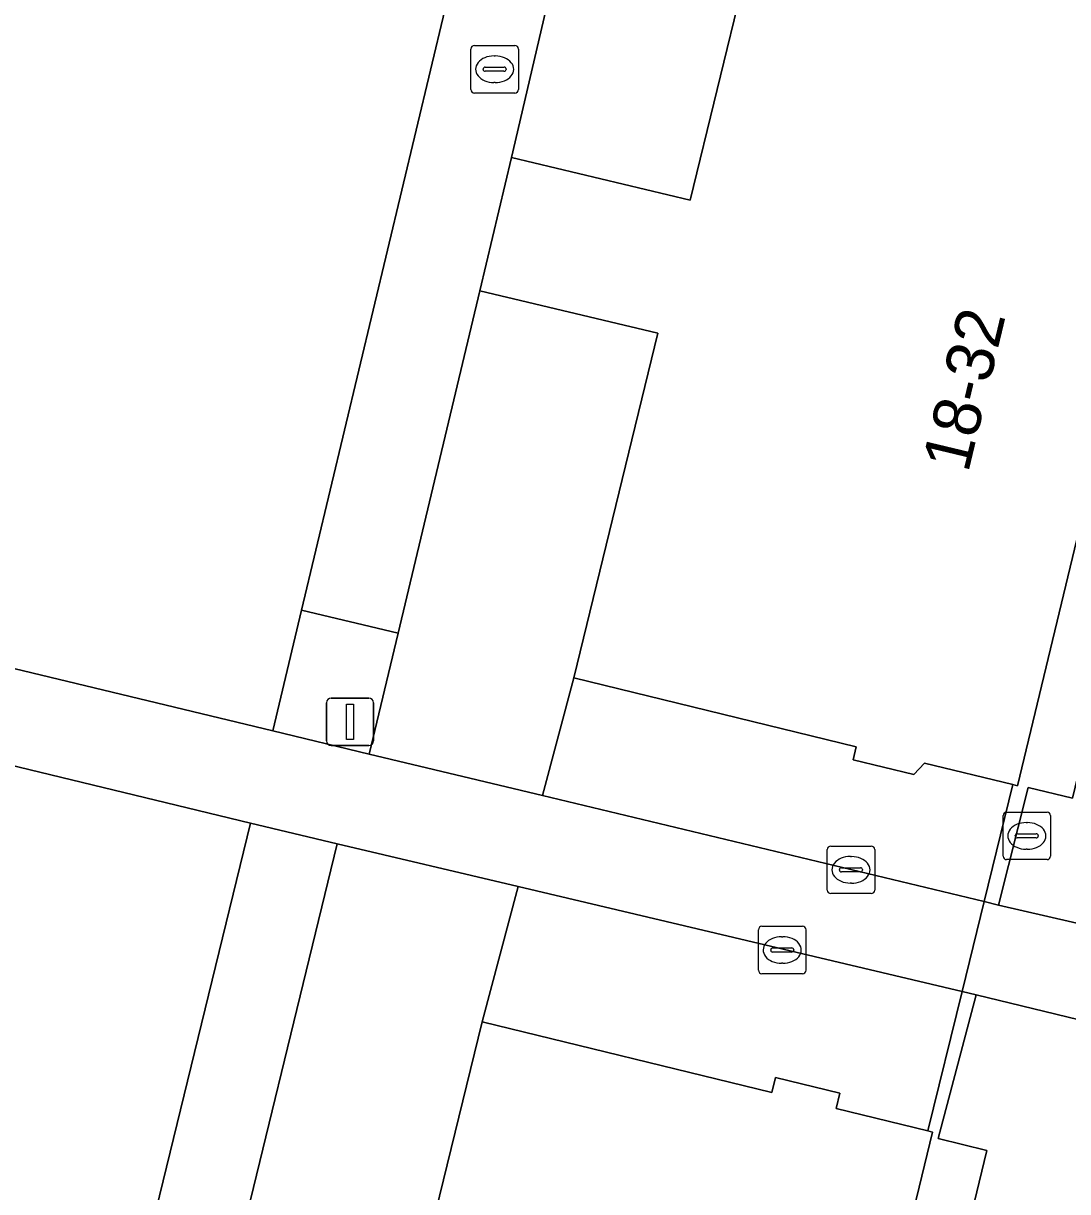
# Model space of a CAD drawing. Extents: x 162803 to 163818, y 381639 to 382475.
# Drawn here: x 163067.19 to 163089.17, y 382297.45 to 382322.05 of the extents above; entities that cross this region are included whole.
import ezdxf

# ---------------------------------------------------------------- set-up
doc = ezdxf.new("R2010")
doc.units = 0
for name, color, linetype in [('IMGEO_Erf', 7, 'Continuous'), ('IMGEO_Hek', 7, 'Continuous'), ('IMGEO_Kolk', 7, 'Continuous'), ('IMGEO_Lichtmast', 7, 'Continuous'), ('IMGEO_Pand', 7, 'Continuous'), ('IMGEO_Pand_nummerreeks', 7, 'Continuous'), ('IMGEO_Rijbaan_lokaal_open', 7, 'Continuous'), ('IMGEO_Rioolput', 7, 'Continuous'), ('IMGEO_Voetpad_open', 7, 'Continuous')]:
    doc.layers.add(name, color=color, linetype=linetype)

msp = doc.modelspace()

# ---------------------------------------------------------------- linework, layer by layer
at = {"layer": 'IMGEO_Erf'}
for points in [[(163047.148, 382313.237), (163050.064, 382312.535), (163072.437, 382307.153), (163073.044, 382309.695), (163078.774, 382333.702), (163080.732, 382333.247), (163081.463, 382336.312), (163085.348, 382335.385), (163086.911, 382341.81), (163082.923, 382342.771), (163082.98, 382343.013), (163078.703, 382344.022), (163078.603, 382343.596), (163074.714, 382344.513)], [(163048.239, 382218.67), (163052.52, 382217.651), (163052.587, 382217.933), (163056.662, 382216.932), (163057.383, 382219.931), (163058.384, 382224.091), (163054.451, 382225.06), (163052.509, 382225.538), (163058.483, 382250), (163071.966, 382305.208), (163049.551, 382310.636), (163046.613, 382311.37)]]:
    msp.add_lwpolyline(points, dxfattribs=at)
for points in [[(163084.627, 382332.317), (163080.732, 382333.247), (163077.463, 382319.223), (163081.222, 382318.327), (163082.925, 382325.322)], [(163080.542, 382315.527), (163076.795, 382316.421), (163075.074, 382309.213), (163074.466, 382306.666), (163078.114, 382305.79), (163078.775, 382308.268)], [(163086.158, 382306.473), (163085.931, 382306.236), (163084.652, 382306.547), (163084.719, 382306.821), (163078.775, 382308.268), (163078.114, 382305.79), (163087.41, 382303.559), (163088.014, 382306.022)], [(163076.842, 382301.026), (163077.602, 382303.874), (163073.795, 382304.774), (163071.315, 382294.597), (163075.048, 382293.685)], [(163086.946, 382301.665), (163077.602, 382303.874), (163076.842, 382301.026), (163082.941, 382299.537), (163083.02, 382299.859), (163084.377, 382299.528), (163084.297, 382299.201), (163086.227, 382298.73)]]:
    msp.add_lwpolyline(points, close=True, dxfattribs=at)
at = {"layer": 'IMGEO_Hek'}
for points in [[(163088.014, 382306.022), (163087.41, 382303.559)], [(163087.41, 382303.559), (163086.946, 382301.665)], [(163086.946, 382301.665), (163086.227, 382298.73)]]:
    msp.add_lwpolyline(points, dxfattribs=at)
at = {"layer": 'IMGEO_Kolk'}
for p, q in [((163084.182, 382304.728), (163085.034, 382304.728)), ((163084.107, 382303.802), (163084.107, 382304.654)), ((163084.595, 382304.508), (163084.62, 382304.508)), ((163085.108, 382304.654), (163085.108, 382303.802)), ((163084.366, 382304.222), (163084.366, 382304.234)), ((163084.409, 382304.271), (163084.807, 382304.271)), ((163084.85, 382304.234), (163084.85, 382304.222)), ((163084.804, 382304.185), (163084.406, 382304.185)), ((163085.034, 382303.728), (163084.182, 382303.728)), ((163084.618, 382303.948), (163084.593, 382303.948)), ((163082.735, 382303.04), (163083.587, 382303.04)), ((163082.66, 382302.114), (163082.66, 382302.966)), ((163083.148, 382302.82), (163083.173, 382302.82)), ((163083.661, 382302.966), (163083.661, 382302.114)), ((163082.919, 382302.534), (163082.919, 382302.546)), ((163083.357, 382302.497), (163082.959, 382302.497)), ((163082.962, 382302.583), (163083.36, 382302.583)), ((163083.403, 382302.546), (163083.403, 382302.534)), ((163083.171, 382302.26), (163083.146, 382302.26)), ((163083.587, 382302.04), (163082.735, 382302.04))]:
    msp.add_line(p, q, dxfattribs=at)
for points in [[(163084.182, 382304.728), (163085.034, 382304.728)], [(163084.107, 382303.802), (163084.107, 382304.654)], [(163085.108, 382304.654), (163085.108, 382303.802)], [(163085.034, 382303.728), (163084.182, 382303.728)], [(163082.735, 382303.04), (163083.587, 382303.04)], [(163082.66, 382302.114), (163082.66, 382302.966)], [(163083.661, 382302.966), (163083.661, 382302.114)], [(163083.587, 382302.04), (163082.735, 382302.04)]]:
    msp.add_lwpolyline(points, dxfattribs=at)
for centre, radius, start, end in [((163084.184, 382304.652), 0.0765, 91.552, 178.448), ((163084.184, 382304.652), 0.0765, 91.552, 178.448), ((163085.032, 382304.652), 0.0765, 1.552, 88.448), ((163085.032, 382304.652), 0.0765, 1.552, 88.448), ((163084.406, 382304.231), 0.0403, 85.8775, 175.7526), ((163084.403, 382304.221), 0.0366, 178.938, 274.7102), ((163084.807, 382304.228), 0.043, 264.8664, 352.4533), ((163084.811, 382304.233), 0.0386, 1.7309, 96.639), ((163084.184, 382303.804), 0.0765, 181.552, 268.448), ((163084.184, 382303.804), 0.0765, 181.552, 268.448), ((163085.032, 382303.804), 0.0765, 271.552, 358.448), ((163085.032, 382303.804), 0.0765, 271.552, 358.448), ((163082.737, 382302.964), 0.0765, 91.552, 178.448), ((163082.737, 382302.964), 0.0765, 91.552, 178.448), ((163083.585, 382302.964), 0.0765, 1.552, 88.448), ((163083.585, 382302.964), 0.0765, 1.552, 88.448), ((163082.959, 382302.543), 0.0403, 85.8775, 175.7526), ((163082.956, 382302.533), 0.0366, 178.938, 274.7102), ((163083.36, 382302.54), 0.043, 264.8664, 352.4533), ((163083.364, 382302.545), 0.0386, 1.7309, 96.639), ((163082.737, 382302.116), 0.0765, 181.552, 268.448), ((163082.737, 382302.116), 0.0765, 181.552, 268.448), ((163083.585, 382302.116), 0.0765, 271.552, 358.448), ((163083.585, 382302.116), 0.0765, 271.552, 358.448)]:
    msp.add_arc(centre, radius, start, end, dxfattribs=at)
for centre, major_axis, ratio, start_param, end_param in [((163084.594, 382304.228), (-0.387, 0.002), 0.722429, 4.712389, 7.853982), ((163084.619, 382304.228), (-0.39, 0.002), 0.717154, 1.570796, 4.712389), ((163083.147, 382302.54), (-0.387, 0.002), 0.722429, 4.712389, 7.853982), ((163083.172, 382302.54), (-0.39, 0.002), 0.717154, 1.570796, 4.712389)]:
    msp.add_ellipse(centre, major_axis=major_axis, ratio=ratio, start_param=start_param, end_param=end_param, dxfattribs=at)
at = {"layer": 'IMGEO_Lichtmast'}
for p, q in [((163073.567, 382306.944), (163073.567, 382307.744)), ((163073.567, 382307.744), (163073.567, 382306.944)), ((163073.667, 382307.844), (163074.457, 382307.844)), ((163074.457, 382307.844), (163073.667, 382307.844)), ((163074.557, 382307.744), (163074.557, 382306.944)), ((163074.557, 382306.944), (163074.557, 382307.744)), ((163074.457, 382306.844), (163073.667, 382306.844)), ((163073.667, 382306.844), (163074.457, 382306.844))]:
    msp.add_line(p, q, dxfattribs=at)
msp.add_lwpolyline([(163073.987, 382307.719), (163074.137, 382307.719), (163074.137, 382306.969), (163073.987, 382306.969), (163073.987, 382307.719)], dxfattribs=at)
for centre, start, end in [((163073.667, 382307.744), 90, 180), ((163073.667, 382307.744), 90, 180), ((163074.457, 382307.744), 0, 90), ((163074.457, 382307.744), 360, 90), ((163073.667, 382306.944), 180, 270), ((163073.667, 382306.944), 180, 270), ((163074.457, 382306.944), 270, 0), ((163074.457, 382306.944), 270, 0)]:
    msp.add_arc(centre, 0.1, start, end, dxfattribs=at)
at = {"layer": 'IMGEO_Pand'}
for points in [[(163092.229, 382323.079), (163082.925, 382325.322), (163081.222, 382318.327), (163077.463, 382319.223), (163076.795, 382316.421), (163080.542, 382315.527), (163078.775, 382308.268), (163084.719, 382306.821), (163084.652, 382306.547), (163085.931, 382306.236), (163086.158, 382306.473), (163088.014, 382306.022), (163088.111, 382305.998)], [(163072.673, 382283.908), (163082.175, 382281.603), (163086.324, 382298.706), (163086.227, 382298.73), (163084.297, 382299.201), (163084.377, 382299.528), (163083.02, 382299.859), (163082.941, 382299.537), (163076.842, 382301.026), (163075.048, 382293.685), (163071.315, 382294.597), (163070.655, 382291.891), (163074.4, 382290.976)]]:
    msp.add_lwpolyline(points, close=True, dxfattribs=at)
at = {"layer": 'IMGEO_Rijbaan_lokaal_open'}
msp.add_lwpolyline([(163090.313, 382302.887), (163087.716, 382303.486), (163087.41, 382303.559), (163086.946, 382301.665), (163087.242, 382301.595), (163089.872, 382300.961)], dxfattribs=at)
at = {"layer": 'IMGEO_Rioolput'}
for p, q in [((163076.606, 382320.657), (163076.606, 382321.509)), ((163076.681, 382321.583), (163077.533, 382321.583)), ((163077.607, 382321.509), (163077.607, 382320.657)), ((163077.094, 382321.363), (163077.119, 382321.363)), ((163076.865, 382321.077), (163076.865, 382321.089)), ((163077.303, 382321.04), (163076.905, 382321.04)), ((163076.908, 382321.126), (163077.306, 382321.126)), ((163077.349, 382321.089), (163077.349, 382321.077)), ((163077.117, 382320.803), (163077.092, 382320.803)), ((163077.533, 382320.583), (163076.681, 382320.583)), ((163087.884, 382305.443), (163088.736, 382305.443)), ((163087.809, 382304.517), (163087.809, 382305.369)), ((163088.297, 382305.223), (163088.322, 382305.223)), ((163088.81, 382305.369), (163088.81, 382304.517)), ((163088.068, 382304.937), (163088.068, 382304.949)), ((163088.111, 382304.986), (163088.509, 382304.986)), ((163088.552, 382304.949), (163088.552, 382304.937)), ((163088.506, 382304.9), (163088.108, 382304.9)), ((163088.736, 382304.443), (163087.884, 382304.443)), ((163088.32, 382304.663), (163088.295, 382304.663))]:
    msp.add_line(p, q, dxfattribs=at)
for points in [[(163076.606, 382320.657), (163076.606, 382321.509)], [(163076.681, 382321.583), (163077.533, 382321.583)], [(163077.607, 382321.509), (163077.607, 382320.657)], [(163077.533, 382320.583), (163076.681, 382320.583)], [(163087.884, 382305.443), (163088.736, 382305.443)], [(163087.809, 382304.517), (163087.809, 382305.369)], [(163088.81, 382305.369), (163088.81, 382304.517)], [(163088.736, 382304.443), (163087.884, 382304.443)]]:
    msp.add_lwpolyline(points, dxfattribs=at)
for centre, radius, start, end in [((163076.683, 382321.507), 0.0765, 91.552, 178.448), ((163076.683, 382321.507), 0.0765, 91.552, 178.448), ((163077.531, 382321.507), 0.0765, 1.552, 88.448), ((163077.531, 382321.507), 0.0765, 1.552, 88.448), ((163076.905, 382321.086), 0.0403, 85.8775, 175.7526), ((163076.902, 382321.076), 0.0366, 178.938, 274.7102), ((163077.306, 382321.083), 0.043, 264.8664, 352.4533), ((163077.31, 382321.088), 0.0386, 1.7309, 96.639), ((163076.683, 382320.659), 0.0765, 181.552, 268.448), ((163076.683, 382320.659), 0.0765, 181.552, 268.448), ((163077.531, 382320.659), 0.0765, 271.552, 358.448), ((163077.531, 382320.659), 0.0765, 271.552, 358.448), ((163087.886, 382305.367), 0.0765, 91.552, 178.448), ((163087.886, 382305.367), 0.0765, 91.552, 178.448), ((163088.734, 382305.367), 0.0765, 1.552, 88.448), ((163088.734, 382305.367), 0.0765, 1.552, 88.448), ((163088.108, 382304.946), 0.0403, 85.8775, 175.7526), ((163088.105, 382304.936), 0.0366, 178.938, 274.7102), ((163088.509, 382304.943), 0.043, 264.8664, 352.4533), ((163088.513, 382304.948), 0.0386, 1.7309, 96.639), ((163087.886, 382304.519), 0.0765, 181.552, 268.448), ((163087.886, 382304.519), 0.0765, 181.552, 268.448), ((163088.734, 382304.519), 0.0765, 271.552, 358.448), ((163088.734, 382304.519), 0.0765, 271.552, 358.448)]:
    msp.add_arc(centre, radius, start, end, dxfattribs=at)
for centre, major_axis, ratio, start_param, end_param in [((163077.093, 382321.083), (-0.387, 0.002), 0.722429, 4.712389, 7.853982), ((163077.118, 382321.083), (-0.39, 0.002), 0.717154, 1.570796, 4.712389), ((163088.296, 382304.943), (-0.387, 0.002), 0.722429, 4.712389, 7.853982), ((163088.321, 382304.943), (-0.39, 0.002), 0.717154, 1.570796, 4.712389)]:
    msp.add_ellipse(centre, major_axis=major_axis, ratio=ratio, start_param=start_param, end_param=end_param, dxfattribs=at)
at = {"layer": 'IMGEO_Voetpad_open'}
for points in [[(163098.21, 382342.619), (163097.513, 382339.742), (163089.27, 382305.738), (163088.337, 382305.961), (163087.716, 382303.486), (163090.313, 382302.887)], [(163089.872, 382300.961), (163087.242, 382301.595), (163086.447, 382298.575), (163087.465, 382298.318), (163075.774, 382250), (163067.591, 382216.313), (163067.07, 382214.116), (163066.453, 382212.54), (163065.195, 382207.154), (163065.124, 382206.864), (163069.755, 382205.884), (163070.225, 382207.754), (163070.948, 382210.415)]]:
    msp.add_lwpolyline(points, dxfattribs=at)
for points in [[(163087.716, 382303.486), (163088.337, 382305.961), (163089.27, 382305.738), (163097.513, 382339.742), (163096.319, 382340.044), (163092.229, 382323.079), (163088.111, 382305.998), (163088.014, 382306.022), (163087.41, 382303.559)], [(163075.074, 382309.213), (163076.795, 382316.421), (163077.463, 382319.223), (163080.732, 382333.247), (163078.774, 382333.702), (163073.044, 382309.695)], [(163050.064, 382312.535), (163047.148, 382313.237), (163045.194, 382313.707), (163041.453, 382314.607), (163032.307, 382316.807), (163031.796, 382314.758), (163040.997, 382312.703), (163044.624, 382311.811), (163046.613, 382311.37), (163049.551, 382310.636), (163071.966, 382305.208), (163073.795, 382304.774), (163077.602, 382303.874), (163086.946, 382301.665), (163087.41, 382303.559), (163078.114, 382305.79), (163074.466, 382306.666), (163072.437, 382307.153)], [(163073.044, 382309.695), (163072.437, 382307.153), (163074.466, 382306.666), (163075.074, 382309.213)], [(163066.557, 382275.073), (163067.21, 382277.754), (163070.655, 382291.891), (163071.315, 382294.597), (163073.795, 382304.774), (163071.966, 382305.208), (163058.483, 382250), (163052.509, 382225.538), (163054.451, 382225.06), (163055.102, 382227.701), (163058.587, 382241.859), (163059.237, 382244.5), (163060.575, 382250), (163062.469, 382258.3), (163063.152, 382261.102)], [(163086.946, 382301.665), (163086.227, 382298.73), (163086.324, 382298.706), (163082.175, 382281.603), (163078.114, 382264.863), (163074.508, 382250), (163073.948, 382247.695), (163070.034, 382231.565), (163065.869, 382214.405), (163067.07, 382214.116), (163067.591, 382216.313), (163075.774, 382250), (163087.465, 382298.318), (163086.447, 382298.575), (163087.242, 382301.595)]]:
    msp.add_lwpolyline(points, close=True, dxfattribs=at)

# ---------------------------------------------------------------- texts
at = {"layer": 'IMGEO_Pand_nummerreeks'}
msp.add_text('18-32', height=1, rotation=76.5544, dxfattribs=at).set_placement((163087.073, 382312.566))

doc.saveas('drawing.dxf')
